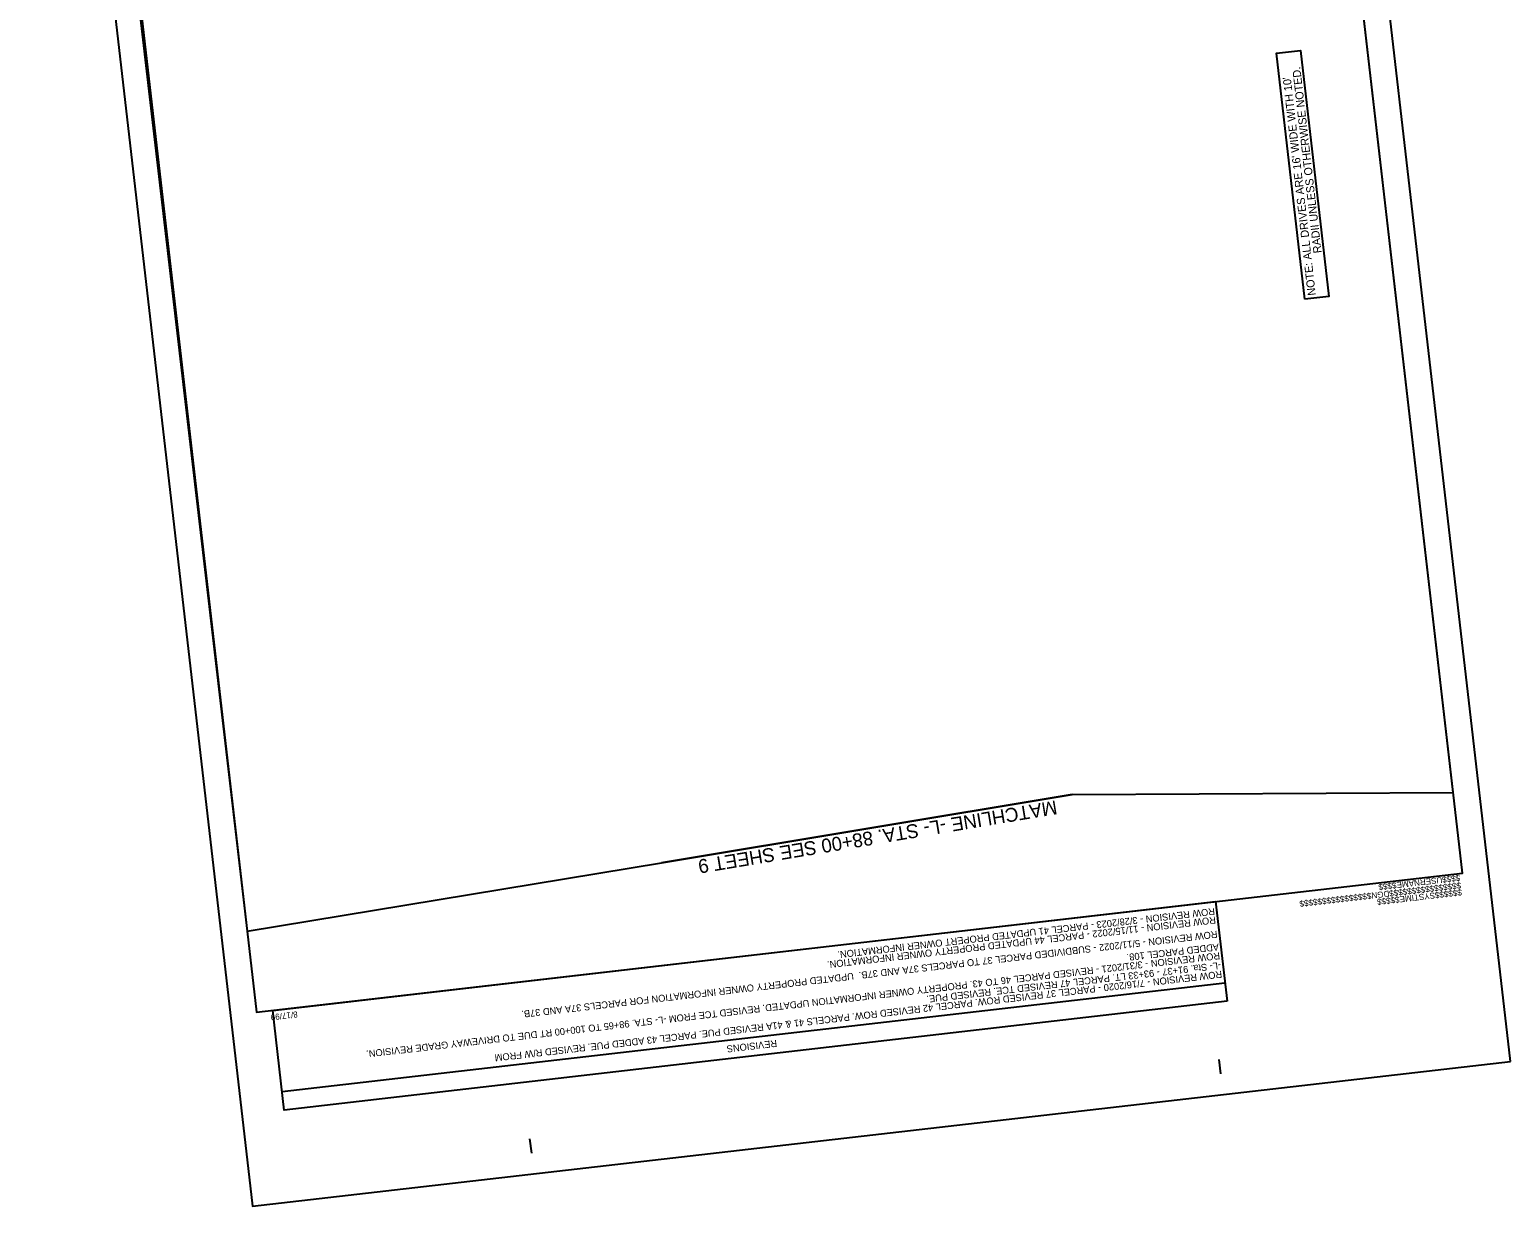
# Model space of a CAD drawing. Extents: x 477658 to 478938, y 495105 to 496902.
# Drawn here: x 477658 to 478938, y 495105 to 496123 of the extents above; entities that cross this region are included whole.
import ezdxf

# ---------------------------------------------------------------- set-up
doc = ezdxf.new("R2010")
doc.units = 0
for name, color, linetype in [('Matchline', 7, 'Continuous'), ('Matchline Text', 7, 'Continuous'), ('Prop DSN Text', 7, 'Continuous'), ('Prop Grid Mask', 7, 'Continuous'), ('Sheet Block Revision CELL', 7, 'Continuous'), ('Sheet Clip Boundary CELL', 7, 'Continuous'), ('Sheet Plan CELL', 7, 'Continuous'), ('Sheet Plot Border Outside CELL', 7, 'Continuous')]:
    doc.layers.add(name, color=color, linetype=linetype)

msp = doc.modelspace()

# ---------------------------------------------------------------- linework, layer by layer
at = {"layer": 'Matchline'}
msp.add_line((478559.2, 495461), (478204.1, 495401.9), dxfattribs=at)
at = {"layer": 'Prop Grid Mask'}
msp.add_lwpolyline([(478760.6, 495889.3), (478736, 496102.2), (478756.9, 496104.6), (478781.4, 495891.7)], close=True, dxfattribs=at)
at = {"layer": 'Sheet Block Revision CELL'}
msp.add_line((478691.4, 495297.6), (477876, 495203.6), dxfattribs=at)
msp.add_lwpolyline([(478693.3, 495282.1), (477877.8, 495188), (477867.9, 495274.2), (478683.3, 495368.3)], close=True, dxfattribs=at)
at = {"layer": 'Sheet Clip Boundary CELL'}
msp.add_lwpolyline([(477845.7, 495342.6), (478204.1, 495401.9), (478559.2, 495461), (478888.8, 495462.8), (478777.8, 496425.5), (478728.9, 496419.8), (478695.7, 496707.9), (478665.1, 496704.4), (478657.2, 496772.7), (478394.8, 496743), (478037.7, 496697.4), (477976.1, 496642.4), (477981, 496608.6), (477984.2, 496582.6), (477880.2, 496558.9), (477880.2, 496558.9), (477704.5, 496550)], close=True, dxfattribs=at)
at = {"layer": 'Sheet Plan CELL'}
for p, q in [((478896.9, 495392.9), (478896.9, 495392.9)), ((477853.8, 495272.6), (477853.8, 495272.6)), ((478687.9, 495219.3), (478686.5, 495231.8)), ((478091.9, 495150.6), (478090.4, 495163))]:
    msp.add_line(p, q, dxfattribs=at)
msp.add_lwpolyline([(477682, 496762.8), (477853.8, 495272.6), (478896.9, 495392.9), (478725.1, 496883)], close=True, dxfattribs=at)
at = {"layer": 'Sheet Plot Border Outside CELL'}
msp.add_lwpolyline([(478938.3, 495230.1), (478745.5, 496902.5), (477657.7, 496777.1), (477850.5, 495104.7)], close=True, dxfattribs=at)

# ---------------------------------------------------------------- texts
at = {"layer": 'Matchline Text'}
msp.add_text('MATCHLINE -L- STA. 88+00 SEE SHEET 9', height=12, rotation=189.4371, dxfattribs=at).set_placement((478545.2, 495455.9))
at = {"layer": 'Prop DSN Text'}
for s, p in [('   RADII UNLESS OTHERWISE NOTED. ', (478776, 495921.8)), ("NOTE: ALL DRIVES ARE 16' WIDE WITH 10'", (478770.1, 495892.9))]:
    msp.add_text(s, height=7, rotation=96.5773, dxfattribs=at).set_placement(p)
at = {"layer": 'Sheet Block Revision CELL'}
for s, p in [('ROW REVISION - 3/28/2023 - PARCEL 41 UPDATED PROPERT OWNER INFORMATION. ', (478682.4, 495362.9)), ('ROW REVISION - 11/15/2022 - PARCEL 44 UPDATED PROPERTY OWNER INFORMATION. ', (478683.2, 495355.4)), ('ROW REVISION - 5/11/2022 - SUBDIVIDED PARCEL 37 TO PARCELS 37A AND 37B.  UPDATED PROPERTY OWNER INFORMATION FOR PARCELS 37A AND 37B. ', (478684.6, 495343.1)), ('ROW REVISION - 3/31/2021 - REVISED PARCEL 46 TO 43. PROPERTY OWNER INFORMATION UPDATED. REVISED TCE FROM -L- STA. 98+65 TO 100+00 RT DUE TO DRIVEWAY GRADE REVISION. ', (478686.8, 495324.5)), ('ADDED PARCEL 108. ', (478685.9, 495332.1)), ('ROW REVISION - 7/16/2020 - PARCEL 37 REVISED ROW. PARCEL 42 REVISED ROW. PARCELS 41 & 41A REVISED PUE. PARCEL 43 ADDED PUE. REVISED R/W FROM', (478688.6, 495308.5)), ('-L- Sta. 91+37 - 93+33 LT. PARCEL 47 REVISED TCE. REVISED PUE.', (478687.7, 495316.1)), ('REVISIONS', (478303.7, 495248.7))]:
    msp.add_text(s, height=6, rotation=186.5773, dxfattribs=at).set_placement(p)
at = {"layer": 'Sheet Plan CELL'}
for s, p in [('$$$$$$$$$$$$$$$$DGN$$$$$$$$$$$$$$$$', (478895.4, 495385)), ('$$$$USERNAME$$$$', (478894.6, 495391.5)), ('$$$$$$SYSTIME$$$$$', (478896.1, 495379)), ('8/17/99', (477889.2, 495273.4))]:
    msp.add_text(s, height=5.25, rotation=186.5773, dxfattribs=at).set_placement(p)

doc.saveas('drawing.dxf')
